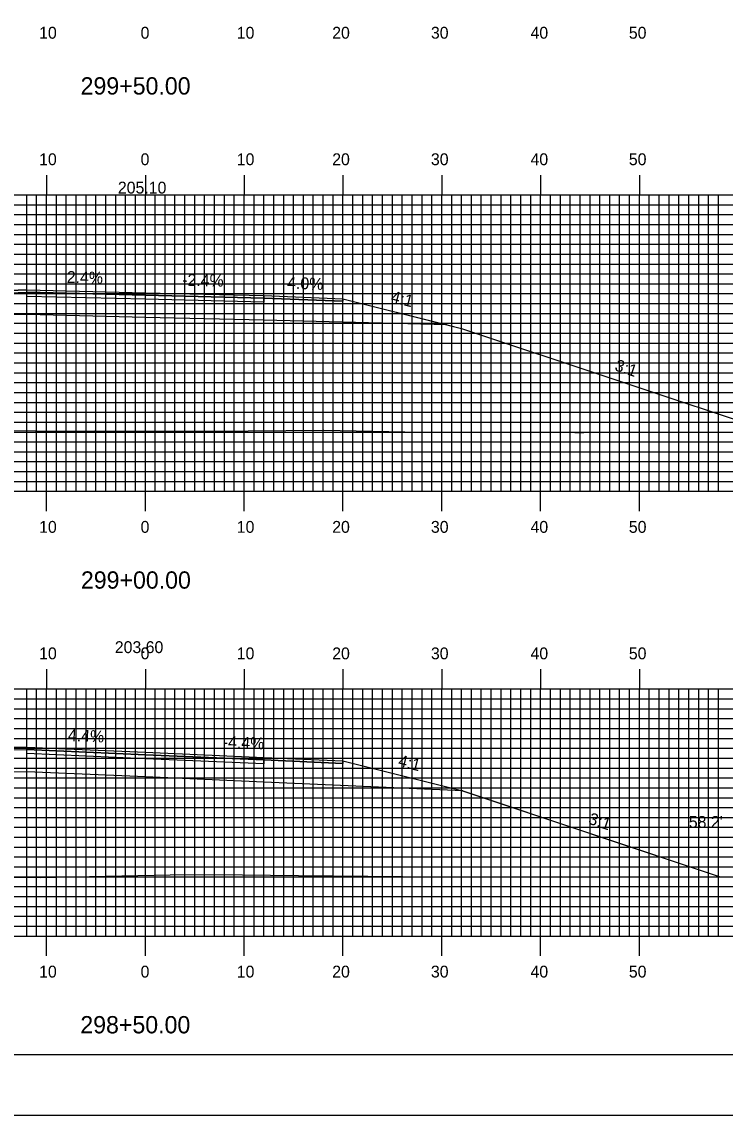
# Model space of a CAD drawing. Extents: x 1815309 to 1815652, y 442591 to 442811.
# Drawn here: x 1815462 to 1815533.2, y 442590.5 to 442701.2 of the extents above; entities that cross this region are included whole.
import ezdxf

# ---------------------------------------------------------------- set-up
doc = ezdxf.new("R2010")
doc.units = 0
for name, color, linetype in [('ANNOTATION', 7, 'Continuous'), ('BORDER', 7, 'Continuous'), ('D_Roadway_Centerline', 7, 'Continuous'), ('D_Roadway_Centerline_Text', 7, 'Continuous'), ('D_Roadway_Edge_Shoulder', 7, 'Continuous'), ('D_Roadway_Edge_TW', 7, 'Continuous'), ('D_Roadway_Pavement', 7, 'Continuous'), ('D_Roadway_SlopeLines', 7, 'Continuous'), ('D_Roadway_SubGrade', 7, 'Continuous'), ('D_Text_Standard', 7, 'Continuous'), ('H_V ANNOTATION', 7, 'Continuous'), ('MAJOR', 7, 'Continuous'), ('MINOR', 7, 'Continuous'), ('PLOT BOUNDARY', 7, 'Continuous'), ('S_Roadway_Centerline', 7, 'Continuous')]:
    doc.layers.add(name, color=color, linetype=linetype)

msp = doc.modelspace()

# ---------------------------------------------------------------- linework, layer by layer
at = {"layer": 'BORDER'}
msp.add_lwpolyline([(1815324.93, 442596.67), (1815644.93, 442596.67), (1815644.93, 442806.67), (1815324.93, 442806.67)], close=True, dxfattribs=at)
at = {"layer": 'D_Roadway_Centerline'}
for points in [[(1815410.41, 442660.06), (1815442.53, 442670.77), (1815444.25, 442671.2), (1815454.53, 442673.77), (1815462.53, 442674.06), (1815474.53, 442673.77), (1815486.53, 442673.48), (1815494.53, 442673.16), (1815505.06, 442670.53), (1815506.53, 442670.16), (1815538.16, 442659.62)], [(1815412.86, 442614.74), (1815442.53, 442624.63), (1815443.66, 442624.92), (1815454.53, 442627.63), (1815462.53, 442627.79), (1815474.53, 442627.27), (1815486.53, 442626.74), (1815494.53, 442626.39), (1815506.53, 442623.39), (1815506.66, 442623.36), (1815532.71, 442614.67)]]:
    msp.add_lwpolyline(points, dxfattribs=at)
at = {"layer": 'D_Roadway_Edge_Shoulder'}
for points in [[(1815462.53, 442674.06), (1815454.53, 442673.77), (1815454.53, 442673.52), (1815462.53, 442673.81)], [(1815486.53, 442673.48), (1815494.53, 442673.16), (1815494.53, 442672.91), (1815486.53, 442673.23)], [(1815462.53, 442627.79), (1815454.53, 442627.63), (1815454.53, 442627.38), (1815462.53, 442627.54)], [(1815486.53, 442626.74), (1815494.53, 442626.39), (1815494.53, 442626.14), (1815486.53, 442626.49)]]:
    msp.add_lwpolyline(points, close=True, dxfattribs=at)
at = {"layer": 'D_Roadway_Edge_TW'}
for points in [[(1815462.53, 442673.81), (1815462.53, 442674.06), (1815474.53, 442673.77), (1815486.53, 442673.48), (1815486.53, 442673.23), (1815474.53, 442673.52)], [(1815462.53, 442627.54), (1815462.53, 442627.79), (1815474.53, 442627.27), (1815486.53, 442626.74), (1815486.53, 442626.49), (1815474.53, 442627.02)]]:
    msp.add_lwpolyline(points, close=True, dxfattribs=at)
at = {"layer": 'D_Roadway_Pavement'}
for points in [[(1815462.53, 442673.39), (1815462.53, 442673.81), (1815474.53, 442673.52), (1815486.53, 442673.23), (1815486.53, 442672.81), (1815474.53, 442673.1)], [(1815462.53, 442627.13), (1815462.53, 442627.54), (1815474.53, 442627.02), (1815486.53, 442626.49), (1815486.53, 442626.08), (1815474.53, 442626.6)]]:
    msp.add_lwpolyline(points, close=True, dxfattribs=at)
at = {"layer": 'D_Roadway_SlopeLines'}
for points in [[(1815494.53, 442673.16), (1815506.53, 442670.16), (1815538.16, 442659.62)], [(1815494.53, 442626.39), (1815506.53, 442623.39), (1815532.71, 442614.67)]]:
    msp.add_lwpolyline(points, dxfattribs=at)
at = {"layer": 'D_Roadway_SubGrade'}
for points in [[(1815462.53, 442671.56), (1815444.25, 442671.2), (1815454.53, 442673.77), (1815454.53, 442673.52), (1815462.53, 442673.81), (1815474.53, 442673.52), (1815486.53, 442673.23), (1815494.53, 442672.91), (1815494.53, 442673.16), (1815505.06, 442670.53), (1815486.53, 442670.98), (1815474.53, 442671.27)], [(1815462.53, 442625.29), (1815443.66, 442624.92), (1815454.53, 442627.63), (1815454.53, 442627.38), (1815462.53, 442627.54), (1815474.53, 442627.02), (1815486.53, 442626.49), (1815494.53, 442626.14), (1815494.53, 442626.39), (1815506.66, 442623.36), (1815486.53, 442624.24), (1815474.53, 442624.77)]]:
    msp.add_lwpolyline(points, close=True, dxfattribs=at)
at = {"layer": 'MAJOR'}
for p, q in [((1815464.53, 442685.67), (1815464.53, 442683.67)), ((1815474.53, 442685.67), (1815474.53, 442683.67)), ((1815484.53, 442685.67), (1815484.53, 442683.67)), ((1815494.53, 442685.67), (1815494.53, 442683.67)), ((1815504.53, 442685.67), (1815504.53, 442683.67)), ((1815514.53, 442685.67), (1815514.53, 442683.67)), ((1815524.53, 442685.67), (1815524.53, 442683.67)), ((1815334.53, 442683.67), (1815614.53, 442683.67)), ((1815334.53, 442683.67), (1815614.53, 442683.67)), ((1815464.53, 442653.67), (1815464.53, 442683.67)), ((1815474.53, 442653.67), (1815474.53, 442683.67)), ((1815484.53, 442653.67), (1815484.53, 442683.67)), ((1815494.53, 442653.67), (1815494.53, 442683.67)), ((1815504.53, 442653.67), (1815504.53, 442683.67)), ((1815514.53, 442653.67), (1815514.53, 442683.67)), ((1815524.53, 442653.67), (1815524.53, 442683.67)), ((1815334.53, 442678.67), (1815614.53, 442678.67)), ((1815334.53, 442673.67), (1815614.53, 442673.67)), ((1815334.53, 442668.67), (1815614.53, 442668.67)), ((1815334.53, 442663.67), (1815614.53, 442663.67)), ((1815334.53, 442658.67), (1815614.53, 442658.67)), ((1815334.53, 442653.67), (1815614.53, 442653.67)), ((1815334.53, 442653.67), (1815614.53, 442653.67)), ((1815464.53, 442651.66), (1815464.53, 442653.67)), ((1815474.53, 442651.66), (1815474.53, 442653.67)), ((1815484.53, 442651.66), (1815484.53, 442653.67)), ((1815494.53, 442651.66), (1815494.53, 442653.67)), ((1815504.53, 442651.66), (1815504.53, 442653.67)), ((1815514.53, 442651.66), (1815514.53, 442653.67)), ((1815524.53, 442651.66), (1815524.53, 442653.67)), ((1815464.53, 442635.67), (1815464.53, 442633.67)), ((1815474.53, 442635.67), (1815474.53, 442633.67)), ((1815484.53, 442635.67), (1815484.53, 442633.67)), ((1815494.53, 442635.67), (1815494.53, 442633.67)), ((1815504.53, 442635.67), (1815504.53, 442633.67)), ((1815514.53, 442635.67), (1815514.53, 442633.67)), ((1815524.53, 442635.67), (1815524.53, 442633.67)), ((1815334.53, 442633.67), (1815614.53, 442633.67)), ((1815334.53, 442633.67), (1815614.53, 442633.67)), ((1815464.53, 442608.67), (1815464.53, 442633.67)), ((1815474.53, 442608.67), (1815474.53, 442633.67)), ((1815484.53, 442608.67), (1815484.53, 442633.67)), ((1815494.53, 442608.67), (1815494.53, 442633.67)), ((1815504.53, 442608.67), (1815504.53, 442633.67)), ((1815514.53, 442608.67), (1815514.53, 442633.67)), ((1815524.53, 442608.67), (1815524.53, 442633.67)), ((1815334.53, 442628.67), (1815614.53, 442628.67)), ((1815334.53, 442623.67), (1815614.53, 442623.67)), ((1815334.53, 442618.67), (1815614.53, 442618.67)), ((1815334.53, 442613.67), (1815614.53, 442613.67)), ((1815334.53, 442608.67), (1815614.53, 442608.67)), ((1815334.53, 442608.67), (1815614.53, 442608.67)), ((1815464.53, 442606.66), (1815464.53, 442608.67)), ((1815474.53, 442606.66), (1815474.53, 442608.67)), ((1815484.53, 442606.66), (1815484.53, 442608.67)), ((1815494.53, 442606.66), (1815494.53, 442608.67)), ((1815504.53, 442606.66), (1815504.53, 442608.67)), ((1815514.53, 442606.66), (1815514.53, 442608.67)), ((1815524.53, 442606.66), (1815524.53, 442608.67))]:
    msp.add_line(p, q, dxfattribs=at)
at = {"layer": 'MINOR'}
for p, q in [((1815462.53, 442653.67), (1815462.53, 442683.67)), ((1815463.53, 442653.67), (1815463.53, 442683.67)), ((1815465.53, 442653.67), (1815465.53, 442683.67)), ((1815466.53, 442653.67), (1815466.53, 442683.67)), ((1815467.53, 442653.67), (1815467.53, 442683.67)), ((1815468.53, 442653.67), (1815468.53, 442683.67)), ((1815469.53, 442653.67), (1815469.53, 442683.67)), ((1815470.53, 442653.67), (1815470.53, 442683.67)), ((1815471.53, 442653.67), (1815471.53, 442683.67)), ((1815472.53, 442653.67), (1815472.53, 442683.67)), ((1815473.53, 442653.67), (1815473.53, 442683.67)), ((1815475.53, 442653.67), (1815475.53, 442683.67)), ((1815476.53, 442653.67), (1815476.53, 442683.67)), ((1815477.53, 442653.67), (1815477.53, 442683.67)), ((1815478.53, 442653.67), (1815478.53, 442683.67)), ((1815479.53, 442653.67), (1815479.53, 442683.67)), ((1815480.53, 442653.67), (1815480.53, 442683.67)), ((1815481.53, 442653.67), (1815481.53, 442683.67)), ((1815482.53, 442653.67), (1815482.53, 442683.67)), ((1815483.53, 442653.67), (1815483.53, 442683.67)), ((1815485.53, 442653.67), (1815485.53, 442683.67)), ((1815486.53, 442653.67), (1815486.53, 442683.67)), ((1815487.53, 442653.67), (1815487.53, 442683.67)), ((1815488.53, 442653.67), (1815488.53, 442683.67)), ((1815489.53, 442653.67), (1815489.53, 442683.67)), ((1815490.53, 442653.67), (1815490.53, 442683.67)), ((1815491.53, 442653.67), (1815491.53, 442683.67)), ((1815492.53, 442653.67), (1815492.53, 442683.67)), ((1815493.53, 442653.67), (1815493.53, 442683.67)), ((1815495.53, 442653.67), (1815495.53, 442683.67)), ((1815496.53, 442653.67), (1815496.53, 442683.67)), ((1815497.53, 442653.67), (1815497.53, 442683.67)), ((1815498.53, 442653.67), (1815498.53, 442683.67)), ((1815499.53, 442653.67), (1815499.53, 442683.67)), ((1815500.53, 442653.67), (1815500.53, 442683.67)), ((1815501.53, 442653.67), (1815501.53, 442683.67)), ((1815502.53, 442653.67), (1815502.53, 442683.67)), ((1815503.53, 442653.67), (1815503.53, 442683.67)), ((1815505.53, 442653.67), (1815505.53, 442683.67)), ((1815506.53, 442653.67), (1815506.53, 442683.67)), ((1815507.53, 442653.67), (1815507.53, 442683.67)), ((1815508.53, 442653.67), (1815508.53, 442683.67)), ((1815509.53, 442653.67), (1815509.53, 442683.67)), ((1815510.53, 442653.67), (1815510.53, 442683.67)), ((1815511.53, 442653.67), (1815511.53, 442683.67)), ((1815512.53, 442653.67), (1815512.53, 442683.67)), ((1815513.53, 442653.67), (1815513.53, 442683.67)), ((1815515.53, 442653.67), (1815515.53, 442683.67)), ((1815516.53, 442653.67), (1815516.53, 442683.67)), ((1815517.53, 442653.67), (1815517.53, 442683.67)), ((1815518.53, 442653.67), (1815518.53, 442683.67)), ((1815519.53, 442653.67), (1815519.53, 442683.67)), ((1815520.53, 442653.67), (1815520.53, 442683.67)), ((1815521.53, 442653.67), (1815521.53, 442683.67)), ((1815522.53, 442653.67), (1815522.53, 442683.67)), ((1815523.53, 442653.67), (1815523.53, 442683.67)), ((1815525.53, 442653.67), (1815525.53, 442683.67)), ((1815526.53, 442653.67), (1815526.53, 442683.67)), ((1815527.53, 442653.67), (1815527.53, 442683.67)), ((1815528.53, 442653.67), (1815528.53, 442683.67)), ((1815529.53, 442653.67), (1815529.53, 442683.67)), ((1815530.53, 442653.67), (1815530.53, 442683.67)), ((1815531.53, 442653.67), (1815531.53, 442683.67)), ((1815532.53, 442653.67), (1815532.53, 442683.67)), ((1815334.53, 442682.67), (1815614.53, 442682.67)), ((1815334.53, 442681.67), (1815614.53, 442681.67)), ((1815334.53, 442680.67), (1815614.53, 442680.67)), ((1815334.53, 442679.67), (1815614.53, 442679.67)), ((1815334.53, 442677.67), (1815614.53, 442677.67)), ((1815334.53, 442676.67), (1815614.53, 442676.67)), ((1815334.53, 442675.67), (1815614.53, 442675.67)), ((1815334.53, 442674.67), (1815614.53, 442674.67)), ((1815334.53, 442672.67), (1815614.53, 442672.67)), ((1815334.53, 442671.67), (1815614.53, 442671.67)), ((1815334.53, 442670.67), (1815614.53, 442670.67)), ((1815334.53, 442669.67), (1815614.53, 442669.67)), ((1815334.53, 442667.67), (1815614.53, 442667.67)), ((1815334.53, 442666.67), (1815614.53, 442666.67)), ((1815334.53, 442665.67), (1815614.53, 442665.67)), ((1815334.53, 442664.67), (1815614.53, 442664.67)), ((1815334.53, 442662.67), (1815614.53, 442662.67)), ((1815334.53, 442661.67), (1815614.53, 442661.67)), ((1815334.53, 442660.67), (1815614.53, 442660.67)), ((1815334.53, 442659.67), (1815614.53, 442659.67)), ((1815334.53, 442657.67), (1815614.53, 442657.67)), ((1815334.53, 442656.67), (1815614.53, 442656.67)), ((1815334.53, 442655.67), (1815614.53, 442655.67)), ((1815334.53, 442654.67), (1815614.53, 442654.67)), ((1815462.53, 442608.67), (1815462.53, 442633.67)), ((1815463.53, 442608.67), (1815463.53, 442633.67)), ((1815465.53, 442608.67), (1815465.53, 442633.67)), ((1815466.53, 442608.67), (1815466.53, 442633.67)), ((1815467.53, 442608.67), (1815467.53, 442633.67)), ((1815468.53, 442608.67), (1815468.53, 442633.67)), ((1815469.53, 442608.67), (1815469.53, 442633.67)), ((1815470.53, 442608.67), (1815470.53, 442633.67)), ((1815471.53, 442608.67), (1815471.53, 442633.67)), ((1815472.53, 442608.67), (1815472.53, 442633.67)), ((1815473.53, 442608.67), (1815473.53, 442633.67)), ((1815475.53, 442608.67), (1815475.53, 442633.67)), ((1815476.53, 442608.67), (1815476.53, 442633.67)), ((1815477.53, 442608.67), (1815477.53, 442633.67)), ((1815478.53, 442608.67), (1815478.53, 442633.67)), ((1815479.53, 442608.67), (1815479.53, 442633.67)), ((1815480.53, 442608.67), (1815480.53, 442633.67)), ((1815481.53, 442608.67), (1815481.53, 442633.67)), ((1815482.53, 442608.67), (1815482.53, 442633.67)), ((1815483.53, 442608.67), (1815483.53, 442633.67)), ((1815485.53, 442608.67), (1815485.53, 442633.67)), ((1815486.53, 442608.67), (1815486.53, 442633.67)), ((1815487.53, 442608.67), (1815487.53, 442633.67)), ((1815488.53, 442608.67), (1815488.53, 442633.67)), ((1815489.53, 442608.67), (1815489.53, 442633.67)), ((1815490.53, 442608.67), (1815490.53, 442633.67)), ((1815491.53, 442608.67), (1815491.53, 442633.67)), ((1815492.53, 442608.67), (1815492.53, 442633.67)), ((1815493.53, 442608.67), (1815493.53, 442633.67)), ((1815495.53, 442608.67), (1815495.53, 442633.67)), ((1815496.53, 442608.67), (1815496.53, 442633.67)), ((1815497.53, 442608.67), (1815497.53, 442633.67)), ((1815498.53, 442608.67), (1815498.53, 442633.67)), ((1815499.53, 442608.67), (1815499.53, 442633.67)), ((1815500.53, 442608.67), (1815500.53, 442633.67)), ((1815501.53, 442608.67), (1815501.53, 442633.67)), ((1815502.53, 442608.67), (1815502.53, 442633.67)), ((1815503.53, 442608.67), (1815503.53, 442633.67)), ((1815505.53, 442608.67), (1815505.53, 442633.67)), ((1815506.53, 442608.67), (1815506.53, 442633.67)), ((1815507.53, 442608.67), (1815507.53, 442633.67)), ((1815508.53, 442608.67), (1815508.53, 442633.67)), ((1815509.53, 442608.67), (1815509.53, 442633.67)), ((1815510.53, 442608.67), (1815510.53, 442633.67)), ((1815511.53, 442608.67), (1815511.53, 442633.67)), ((1815512.53, 442608.67), (1815512.53, 442633.67)), ((1815513.53, 442608.67), (1815513.53, 442633.67)), ((1815515.53, 442608.67), (1815515.53, 442633.67)), ((1815516.53, 442608.67), (1815516.53, 442633.67)), ((1815517.53, 442608.67), (1815517.53, 442633.67)), ((1815518.53, 442608.67), (1815518.53, 442633.67)), ((1815519.53, 442608.67), (1815519.53, 442633.67)), ((1815520.53, 442608.67), (1815520.53, 442633.67)), ((1815521.53, 442608.67), (1815521.53, 442633.67)), ((1815522.53, 442608.67), (1815522.53, 442633.67)), ((1815523.53, 442608.67), (1815523.53, 442633.67)), ((1815525.53, 442608.67), (1815525.53, 442633.67)), ((1815526.53, 442608.67), (1815526.53, 442633.67)), ((1815527.53, 442608.67), (1815527.53, 442633.67)), ((1815528.53, 442608.67), (1815528.53, 442633.67)), ((1815529.53, 442608.67), (1815529.53, 442633.67)), ((1815530.53, 442608.67), (1815530.53, 442633.67)), ((1815531.53, 442608.67), (1815531.53, 442633.67)), ((1815532.53, 442608.67), (1815532.53, 442633.67)), ((1815334.53, 442632.67), (1815614.53, 442632.67)), ((1815334.53, 442631.67), (1815614.53, 442631.67)), ((1815334.53, 442630.67), (1815614.53, 442630.67)), ((1815334.53, 442629.67), (1815614.53, 442629.67)), ((1815334.53, 442627.67), (1815614.53, 442627.67)), ((1815334.53, 442626.67), (1815614.53, 442626.67)), ((1815334.53, 442625.67), (1815614.53, 442625.67)), ((1815334.53, 442624.67), (1815614.53, 442624.67)), ((1815334.53, 442622.67), (1815614.53, 442622.67)), ((1815334.53, 442621.67), (1815614.53, 442621.67)), ((1815334.53, 442620.67), (1815614.53, 442620.67)), ((1815334.53, 442619.67), (1815614.53, 442619.67)), ((1815334.53, 442617.67), (1815614.53, 442617.67)), ((1815334.53, 442616.67), (1815614.53, 442616.67)), ((1815334.53, 442615.67), (1815614.53, 442615.67)), ((1815334.53, 442614.67), (1815614.53, 442614.67)), ((1815334.53, 442612.67), (1815614.53, 442612.67)), ((1815334.53, 442611.67), (1815614.53, 442611.67)), ((1815334.53, 442610.67), (1815614.53, 442610.67)), ((1815334.53, 442609.67), (1815614.53, 442609.67))]:
    msp.add_line(p, q, dxfattribs=at)
at = {"layer": 'PLOT BOUNDARY'}
msp.add_lwpolyline([(1815308.75, 442590.55), (1815648.75, 442590.55), (1815648.75, 442810.55), (1815308.75, 442810.55)], close=True, dxfattribs=at)
at = {"layer": 'S_Roadway_Centerline'}
for points in [[(1815400.23, 442660.28), (1815411.74, 442660.03), (1815422.42, 442659.98), (1815427.06, 442659.83), (1815434.65, 442659.71), (1815439.29, 442659.76), (1815451.58, 442659.96), (1815465.79, 442659.75), (1815469.34, 442659.78), (1815479.38, 442659.77), (1815484.93, 442659.79), (1815492.58, 442659.87), (1815502.45, 442659.67), (1815518.01, 442659.62), (1815518.54, 442659.62), (1815518.67, 442659.62), (1815518.89, 442659.62), (1815536.31, 442659.64)], [(1815398.89, 442615.41), (1815413.38, 442614.72), (1815420.85, 442614.69), (1815430.49, 442614.62), (1815436.18, 442614.61), (1815446.82, 442614.7), (1815457.56, 442614.62), (1815463.97, 442614.59), (1815477.04, 442614.86), (1815481.53, 442614.9), (1815490.04, 442614.81), (1815504.11, 442614.67), (1815514.26, 442614.66), (1815516.61, 442614.68), (1815524.4, 442614.66), (1815532.52, 442614.67), (1815544, 442614.65)]]:
    msp.add_lwpolyline(points, dxfattribs=at)

# ---------------------------------------------------------------- texts
at = {"layer": 'ANNOTATION'}
for s, rotation, p in [('2.4%', 358.607, (1815466.57, 442674.76)), ('-2.4%', 358.607, (1815478.25, 442674.48)), ('-4.0%', 357.7094, (1815488.33, 442674.21)), ('4:1', 345.9638, (1815499.3, 442672.83)), ('3:1', 341.5652, (1815521.95, 442665.93)), ('4.4%', 357.4943, (1815466.68, 442628.41)), ('-4.4%', 357.4942, (1815482.35, 442627.73)), ('4:1', 345.9638, (1815500.04, 442625.88)), ('3:1', 341.5451, (1815519.29, 442620.06))]:
    msp.add_text(s, height=1.2, rotation=rotation, dxfattribs=at).set_placement(p)
at = {"layer": 'D_Roadway_Centerline'}
for s, p in [('C', (1815474.53, 442673.77)), ('L', (1815474.53, 442673.76)), ('C', (1815474.53, 442627.27)), ('L', (1815474.53, 442627.26))]:
    msp.add_text(s, height=0.0146, dxfattribs=at).set_placement(p)
at = {"layer": 'D_Roadway_Centerline_Text'}
for s, p in [('205.10', (1815471.75, 442683.8)), ('203.60', (1815471.44, 442637.3))]:
    msp.add_text(s, height=1.2, dxfattribs=at).set_placement(p)
at = {"layer": 'D_Text_Standard'}
msp.add_text("58.2'", height=1.2, dxfattribs=at).set_placement((1815529.53, 442619.61))
at = {"layer": 'H_V ANNOTATION'}
for s, height, p in [('10', 1.2, (1815463.78, 442699.47)), ('0', 1.2, (1815474.05, 442699.47)), ('10', 1.2, (1815483.78, 442699.47)), ('20', 1.2, (1815493.44, 442699.47)), ('30', 1.2, (1815503.43, 442699.47)), ('40', 1.2, (1815513.51, 442699.47)), ('50', 1.2, (1815523.46, 442699.47)), ('299+50.00', 1.75, (1815467.98, 442693.82)), ('10', 1.2, (1815463.78, 442686.67)), ('0', 1.2, (1815474.05, 442686.67)), ('10', 1.2, (1815483.78, 442686.67)), ('20', 1.2, (1815493.44, 442686.67)), ('30', 1.2, (1815503.43, 442686.67)), ('40', 1.2, (1815513.51, 442686.67)), ('50', 1.2, (1815523.46, 442686.67)), ('10', 1.2, (1815463.78, 442649.47)), ('0', 1.2, (1815474.05, 442649.47)), ('10', 1.2, (1815483.78, 442649.47)), ('20', 1.2, (1815493.44, 442649.47)), ('30', 1.2, (1815503.43, 442649.47)), ('40', 1.2, (1815513.51, 442649.47)), ('50', 1.2, (1815523.46, 442649.47)), ('299+00.00', 1.75, (1815468.01, 442643.82)), ('10', 1.2, (1815463.78, 442636.67)), ('0', 1.2, (1815474.05, 442636.67)), ('10', 1.2, (1815483.78, 442636.67)), ('20', 1.2, (1815493.44, 442636.67)), ('30', 1.2, (1815503.43, 442636.67)), ('40', 1.2, (1815513.51, 442636.67)), ('50', 1.2, (1815523.46, 442636.67)), ('10', 1.2, (1815463.78, 442604.47)), ('0', 1.2, (1815474.05, 442604.47)), ('10', 1.2, (1815483.78, 442604.47)), ('20', 1.2, (1815493.44, 442604.47)), ('30', 1.2, (1815503.43, 442604.47)), ('40', 1.2, (1815513.51, 442604.47)), ('50', 1.2, (1815523.46, 442604.47)), ('298+50.00', 1.75, (1815467.95, 442598.82))]:
    msp.add_text(s, height=height, dxfattribs=at).set_placement(p)

doc.saveas('drawing.dxf')
